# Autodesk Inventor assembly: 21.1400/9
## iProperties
Created: 2006-12
Part Number: 21.1400/9
Document SubType Name: Assembly
Designer: Andy Moles
Description: MACHINE TO PRINT 21.1400/9
Stock Number: 21.1400 MITER CON. N
Vendor: S
Author: Andy Moles
